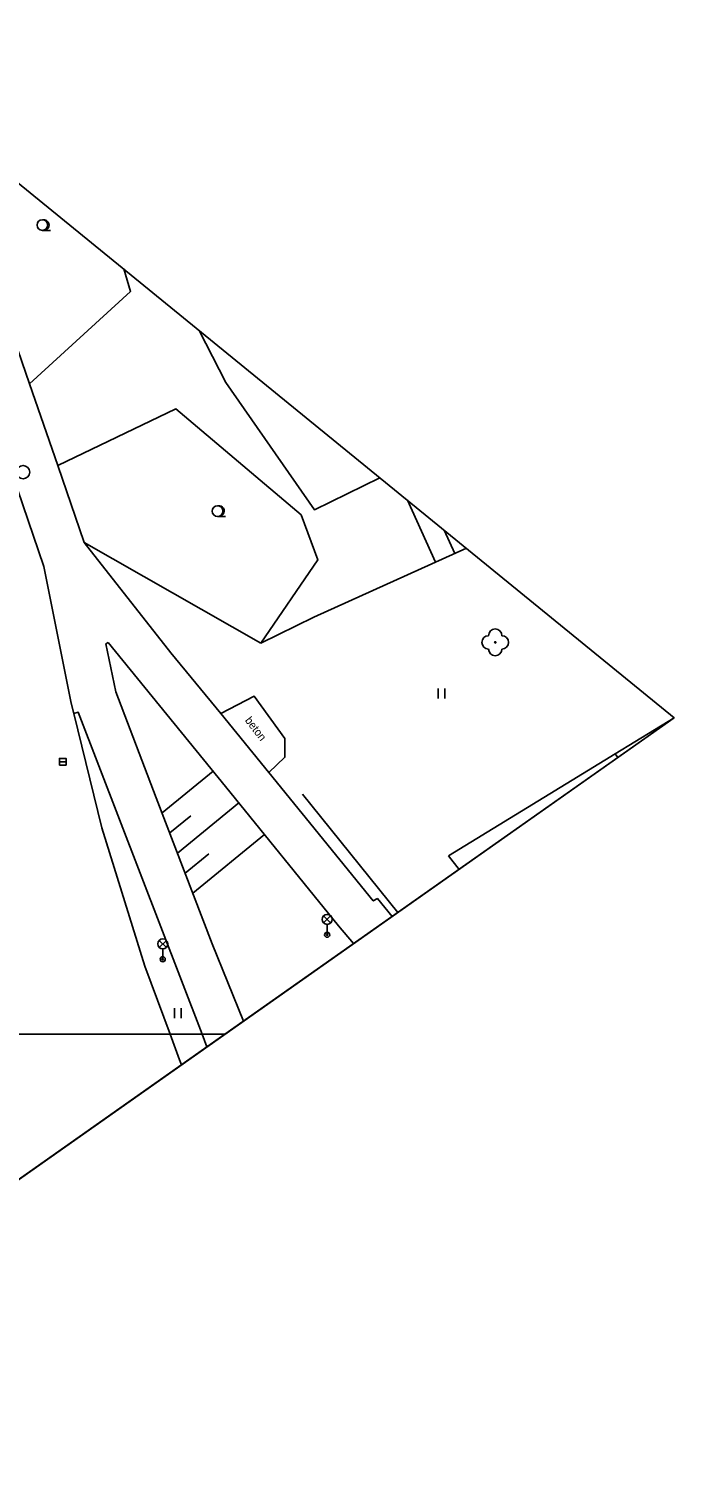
# Model space of a CAD drawing. Extents: x -492431 to -49218, y -1127123 to -112687.
# Drawn here: x -492181.4 to -492133, y -1127032.6 to -1126924.6 of the extents above; entities that cross this region are included whole.
import ezdxf

# ---------------------------------------------------------------- set-up
doc = ezdxf.new("R2010")
doc.units = 0
for name, color, linetype in [('Vrstva 1', 7, 'Continuous'), ('Vrstva 10', 7, 'Continuous'), ('Vrstva 11', 7, 'Continuous'), ('Vrstva 14', 7, 'Continuous'), ('Vrstva 15', 7, 'Continuous'), ('Vrstva 21', 7, 'Continuous'), ('Vrstva 22', 7, 'Continuous'), ('Vrstva 27', 7, 'Continuous'), ('Vrstva 33', 7, 'Continuous'), ('Vrstva 36', 7, 'Continuous'), ('Vrstva 40', 7, 'Continuous'), ('Vrstva 5', 7, 'Continuous'), ('Vrstva 60', 7, 'Continuous'), ('Vrstva 7', 7, 'Continuous')]:
    doc.layers.add(name, color=color, linetype=linetype)

msp = doc.modelspace()

# ---------------------------------------------------------------- linework, layer by layer
at = {"layer": 'Vrstva 1'}
msp.add_lwpolyline([(-492341.24, -1127122.91), (-492133.03, -1126976.26), (-492272.7, -1126862.46), (-492313.78, -1126867.2)], dxfattribs=at)
at = {"layer": 'Vrstva 10'}
for p, q in [((-492177.29, -1126963.12), (-492170.79, -1126971.4)), ((-492175.49, -1126970.63), (-492175.66, -1126970.73)), ((-492175.66, -1126970.73), (-492174.91, -1126974.33)), ((-492166.69, -1126981.42), (-492175.49, -1126970.63)), ((-492174.91, -1126974.33), (-492171.88, -1126982.26)), ((-492171.88, -1126982.26), (-492167.68, -1126993.22)), ((-492166.69, -1126981.42), (-492158.21, -1126991.86)), ((-492157.08, -1126993.2), (-492158.21, -1126991.86)), ((-492167.68, -1126993.22), (-492165.33, -1126999.01))]:
    msp.add_line(p, q, dxfattribs=at)
for points in [[(-492194.65, -1126926.04), (-492191.64, -1126931.65), (-492186.62, -1126946.51), (-492180.32, -1126964.92), (-492178.25, -1126975.18), (-492178.07, -1126975.94)], [(-492183.41, -1126945.33), (-492181.38, -1126951.23), (-492179.27, -1126957.36), (-492177.29, -1126963.12)], [(-492170.79, -1126971.4), (-492167.04, -1126975.94)], [(-492167.04, -1126975.94), (-492164.53, -1126974.65), (-492162.23, -1126977.81), (-492162.23, -1126979.23), (-492163.44, -1126980.36)], [(-492168.44, -1127000), (-492177.73, -1126975.85), (-492178.07, -1126975.94)], [(-492178.07, -1126975.94), (-492175.97, -1126984.53), (-492172.74, -1126994.9), (-492170.84, -1127000)], [(-492163.44, -1126980.36), (-492155.6, -1126990), (-492155.29, -1126989.82), (-492154.18, -1126991.16)], [(-492170.84, -1127000), (-492170.13, -1127001.92), (-492169.98, -1127002.29)], [(-492168.08, -1127000.95), (-492168.44, -1127000)]]:
    msp.add_lwpolyline(points, dxfattribs=at)
at = {"layer": 'Vrstva 11'}
msp.add_line((-492163.44, -1126980.36), (-492167.04, -1126975.94), dxfattribs=at)
at = {"layer": 'Vrstva 14'}
for p, q in [((-492164.03, -1126970.68), (-492177.29, -1126963.12)), ((-492160.05, -1126968.73), (-492164.03, -1126970.68))]:
    msp.add_line(p, q, dxfattribs=at)
for points in [[(-492168.65, -1126947.23), (-492166.66, -1126951.14), (-492160.01, -1126960.67), (-492155.11, -1126958.27)], [(-492160.05, -1126968.73), (-492148.61, -1126963.56)]]:
    msp.add_lwpolyline(points, dxfattribs=at)
at = {"layer": 'Vrstva 15'}
for p, q in [((-492153.03, -1126959.96), (-492150.93, -1126964.6)), ((-492150.28, -1126962.2), (-492149.49, -1126963.95)), ((-492167.62, -1126980.28), (-492171.44, -1126983.4)), ((-492165.69, -1126982.65), (-492170.29, -1126986.41)), ((-492169.29, -1126983.61), (-492170.87, -1126984.9)), ((-492163.76, -1126985.03), (-492169.14, -1126989.42)), ((-492167.94, -1126986.46), (-492169.72, -1126987.91))]:
    msp.add_line(p, q, dxfattribs=at)
at = {"layer": 'Vrstva 21'}
for points in [[(-492174.32, -1126942.61), (-492173.8, -1126944.3), (-492181.38, -1126951.23)], [(-492179.27, -1126957.36), (-492170.41, -1126953.11), (-492161.01, -1126961.06), (-492159.75, -1126964.43), (-492164.03, -1126970.68)]]:
    msp.add_lwpolyline(points, dxfattribs=at)
at = {"layer": 'Vrstva 22'}
msp.add_circle((-492146.45, -1126970.61), 0.05, dxfattribs=at)
for centre, start, end in [((-492146.95, -1126970.61), 90, 270), ((-492146.45, -1126970.11), 360, 180), ((-492145.95, -1126970.61), 270, 90), ((-492146.45, -1126971.11), 180, 0)]:
    msp.add_arc(centre, 0.5, start, end, dxfattribs=at)
at = {"layer": 'Vrstva 27'}
msp.add_line((-492179.14, -1126979.56), (-492178.64, -1126979.56), dxfattribs=at)
msp.add_lwpolyline([(-492179.14, -1126979.81), (-492178.64, -1126979.81), (-492178.64, -1126979.31), (-492179.14, -1126979.31)], close=True, dxfattribs=at)
msp.add_circle((-492181.87, -1126957.85), 0.5, dxfattribs=at)
at = {"layer": 'Vrstva 33'}
for p, q in [((-492159.33, -1126991.11), (-492158.8, -1126991.65)), ((-492159.33, -1126991.65), (-492158.8, -1126991.11)), ((-492159.06, -1126992.53), (-492159.06, -1126991.76)), ((-492171.66, -1126992.96), (-492171.12, -1126993.49)), ((-492171.66, -1126993.49), (-492171.12, -1126992.96)), ((-492171.39, -1126994.37), (-492171.39, -1126993.59))]:
    msp.add_line(p, q, dxfattribs=at)
for centre, radius in [((-492159.06, -1126991.38), 0.375), ((-492171.39, -1126993.22), 0.375), ((-492159.06, -1126992.53), 0.19), ((-492159.06, -1126992.53), 0.05), ((-492171.39, -1126994.37), 0.19), ((-492171.39, -1126994.37), 0.05)]:
    msp.add_circle(centre, radius, dxfattribs=at)
at = {"layer": 'Vrstva 36'}
for p, q in [((-492180.42, -1126939.72), (-492180.32, -1126939.72)), ((-492180.32, -1126939.72), (-492179.82, -1126939.72)), ((-492167.28, -1126961.17), (-492167.18, -1126961.17)), ((-492167.18, -1126961.17), (-492166.68, -1126961.17)), ((-492150.72, -1126974.83), (-492150.72, -1126974.08)), ((-492150.22, -1126974.83), (-492150.22, -1126974.08)), ((-492170.52, -1126998.8), (-492170.52, -1126998.05)), ((-492170.02, -1126998.8), (-492170.02, -1126998.05))]:
    msp.add_line(p, q, dxfattribs=at)
for centre in [(-492180.42, -1126939.32), (-492167.28, -1126960.77)]:
    msp.add_circle(centre, 0.4, dxfattribs=at)
for centre in [(-492180.32, -1126939.32), (-492167.18, -1126960.77)]:
    msp.add_arc(centre, 0.4, 259.6952, 97.1808, dxfattribs=at)
at = {"layer": 'Vrstva 5'}
for p, q in [((-492137.46, -1126978.96), (-492137.26, -1126979.24)), ((-492149.96, -1126986.62), (-492139.46, -1126980.2))]:
    msp.add_line(p, q, dxfattribs=at)
for points in [[(-492133.03, -1126976.26), (-492137.46, -1126978.96)], [(-492137.46, -1126978.96), (-492139.46, -1126980.2)], [(-492149.96, -1126986.62), (-492149.16, -1126987.63)]]:
    msp.add_lwpolyline(points, dxfattribs=at)
at = {"layer": 'Vrstva 60'}
for p, q in [((-492431.03, -1127000), (-492166.73, -1127000)), ((-492166.73, -1127000), (-492431.03, -1127000))]:
    msp.add_line(p, q, dxfattribs=at)
for points in [[(-492166.73, -1127000), (-492133.03, -1126976.26), (-492272.7, -1126862.46), (-492313.78, -1126867.2), (-492431.03, -1126895.43), (-492431.03, -1127000)], [(-492431.03, -1127000), (-492431.03, -1127013.12), (-492341.24, -1127122.91), (-492166.73, -1127000)]]:
    msp.add_lwpolyline(points, dxfattribs=at)
at = {"layer": 'Vrstva 7'}
msp.add_lwpolyline([(-492153.76, -1126990.87), (-492160.92, -1126981.99)], dxfattribs=at)

# ---------------------------------------------------------------- texts
at = {"layer": 'Vrstva 40'}
msp.add_text('beton', height=0.6, rotation=307.3608, dxfattribs=at).set_placement((-492165.26, -1126976.47))

doc.saveas('drawing.dxf')
